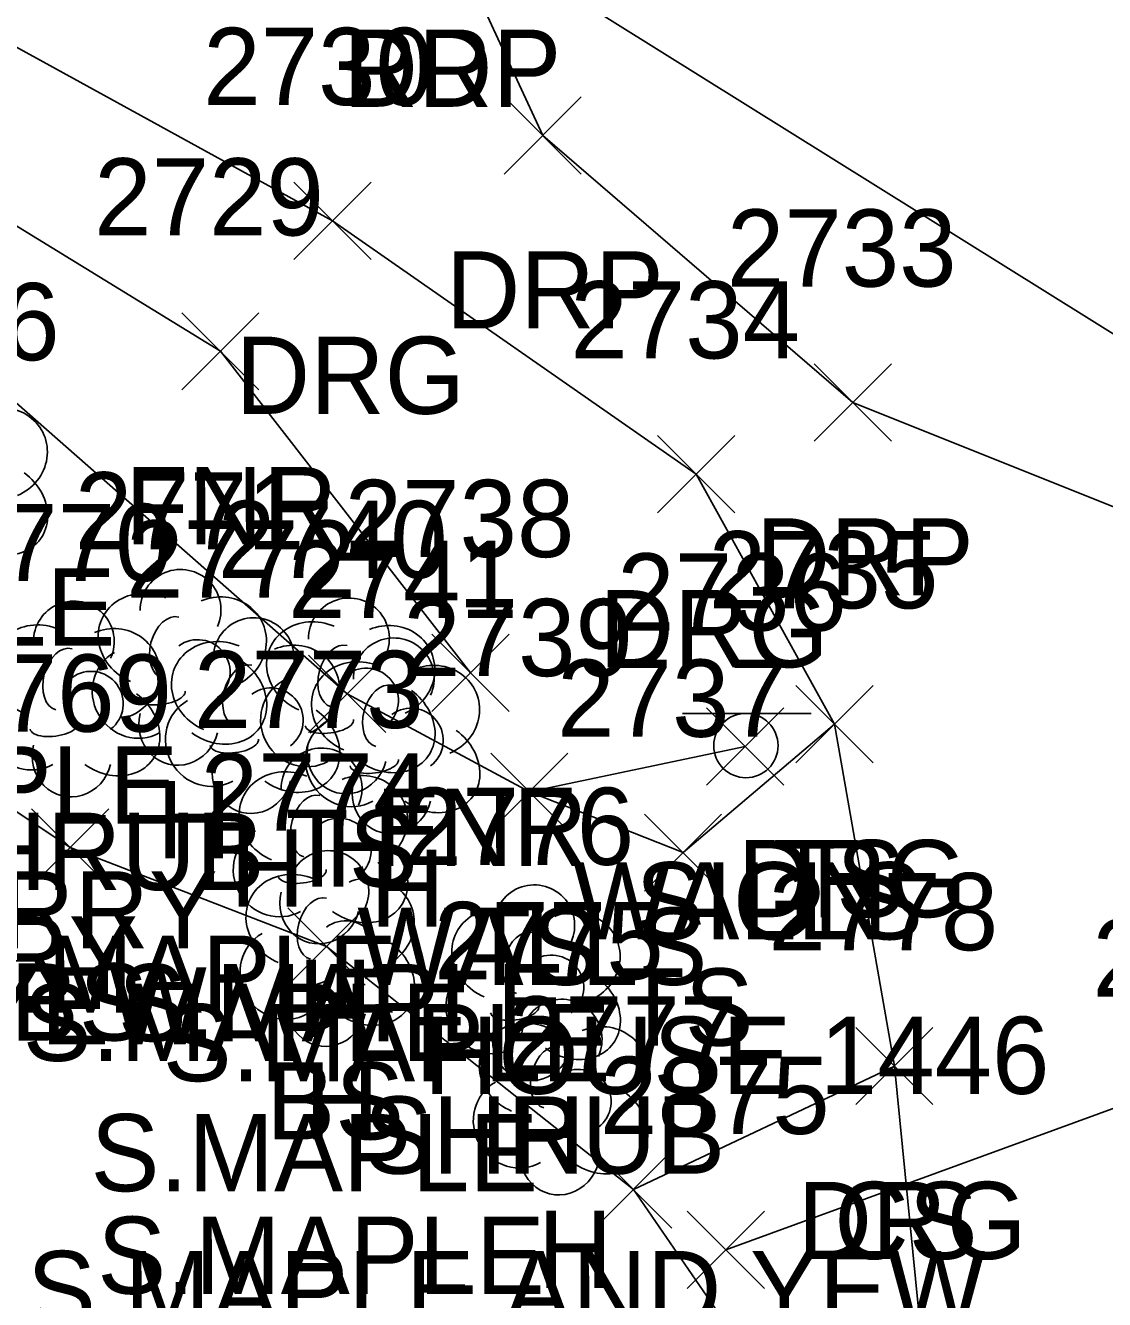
# Model space of a CAD drawing. Extents: x 1499292 to 1501024, y 534584 to 538043.
# Drawn here: x 1499640.28 to 1499668.23, y 537765.66 to 537798.66 of the extents above; entities that cross this region are included whole.
import ezdxf

# ---------------------------------------------------------------- set-up
doc = ezdxf.new("R2010")
doc.units = 0
for name, color, linetype in [('D_I', 7, 'Continuous'), ('D_TIC', 7, 'Continuous'), ('DCP', 7, 'Continuous'), ('L_A', 7, 'Continuous'), ('L_C', 7, 'Continuous'), ('L_I', 7, 'Continuous'), ('L_TIC', 7, 'Continuous'), ('LELB', 7, 'Continuous'), ('LFNC', 7, 'Continuous'), ('LSH', 7, 'Continuous'), ('LTD', 7, 'Continuous'), ('LWS', 7, 'Continuous'), ('P_A', 7, 'Continuous'), ('PET', 7, 'Continuous'), ('R_A', 7, 'Continuous'), ('R_I', 7, 'Continuous'), ('R_TIC', 7, 'Continuous'), ('RDG', 7, 'Continuous'), ('RDP', 7, 'Continuous'), ('S_A', 7, 'Continuous'), ('S_I', 7, 'Continuous'), ('SSGN', 7, 'Continuous'), ('U_C', 7, 'Continuous')]:
    doc.layers.add(name, color=color, linetype=linetype)

msp = doc.modelspace()

# ---------------------------------------------------------------- linework, layer by layer
at = {"layer": 'D_TIC'}
for points in [[(1499657.416, 537765.949), (1499659.416, 537767.949)], [(1499659.416, 537765.949), (1499657.416, 537767.949)]]:
    msp.add_lwpolyline(points, dxfattribs=at)
at = {"layer": 'DCP'}
msp.add_lwpolyline([(1499658.416, 537766.949), (1499674.076, 537772.661)], dxfattribs=at)
at = {"layer": 'L_TIC'}
for points in [[(1499644.323, 537789.222), (1499646.323, 537791.222)], [(1499646.323, 537789.222), (1499644.323, 537791.222)], [(1499650.803, 537780.891), (1499652.803, 537782.891)], [(1499652.803, 537780.891), (1499650.803, 537782.891)], [(1499647.607, 537780.35), (1499649.607, 537782.35)], [(1499649.607, 537780.35), (1499647.607, 537782.35)], [(1499647.607, 537780.35), (1499649.607, 537782.35)], [(1499649.607, 537780.35), (1499647.607, 537782.35)], [(1499660.233, 537779.563), (1499662.233, 537781.563)], [(1499662.233, 537779.563), (1499660.233, 537781.563)], [(1499657.918, 537778.987), (1499659.918, 537780.987)], [(1499659.918, 537778.987), (1499657.918, 537780.987)], [(1499652.328, 537777.808), (1499654.328, 537779.808)], [(1499654.328, 537777.808), (1499652.328, 537779.808)], [(1499652.328, 537777.808), (1499654.328, 537779.808)], [(1499654.328, 537777.808), (1499652.328, 537779.808)], [(1499640.436, 537776.369), (1499642.436, 537778.369)], [(1499642.436, 537776.369), (1499640.436, 537778.369)], [(1499656.308, 537776.236), (1499658.308, 537778.236)], [(1499658.308, 537776.236), (1499656.308, 537778.236)], [(1499647.073, 537773.807), (1499649.073, 537775.807)], [(1499649.073, 537773.807), (1499647.073, 537775.807)], [(1499661.782, 537770.708), (1499663.782, 537772.708)], [(1499663.782, 537770.708), (1499661.782, 537772.708)], [(1499655.022, 537767.512), (1499657.022, 537769.512)], [(1499657.022, 537767.512), (1499655.022, 537769.512)], [(1499655.022, 537767.512), (1499657.022, 537769.512)], [(1499657.022, 537767.512), (1499655.022, 537769.512)]]:
    msp.add_lwpolyline(points, dxfattribs=at)
at = {"layer": 'LELB'}
for points in [[(1499309.186, 537981.429), (1499342.601, 537967.946), (1499383.002, 537948.454), (1499403.335, 537937.322), (1499425.862, 537923.972), (1499462.056, 537903.885), (1499477.958, 537896.437), (1499498.482, 537885.281), (1499524.089, 537871.298), (1499544.155, 537861.141), (1499587.091, 537836.791), (1499598.177, 537827.35), (1499596, 537821.552), (1499610.739, 537811.692), (1499624.068, 537800.087), (1499630.641, 537795.692), (1499636.949, 537791.6), (1499648.607, 537781.35)], [(1499473.284, 537889.721), (1499498.471, 537879.808), (1499498.645, 537874.964), (1499522.472, 537856.451), (1499547.406, 537847.481), (1499543.068, 537839.362), (1499550.539, 537830.456), (1499554.894, 537825.457), (1499558.691, 537827.698), (1499558.309, 537830.261), (1499565.321, 537832.423), (1499575.95, 537829.995), (1499584.046, 537827.015), (1499587.206, 537819.565), (1499598.435, 537808.198), (1499610.893, 537797.818), (1499632.622, 537783.246), (1499641.436, 537777.369), (1499648.073, 537774.807), (1499656.022, 537768.512), (1499664.288, 537756.487)], [(1499661.233, 537780.563), (1499657.308, 537777.236), (1499653.328, 537778.808), (1499648.607, 537781.35)], [(1499656.022, 537768.512), (1499662.782, 537771.708)]]:
    msp.add_lwpolyline(points, dxfattribs=at)
at = {"layer": 'LFNC'}
msp.add_lwpolyline([(1499610.739, 537811.692), (1499626.25, 537801.938), (1499645.323, 537790.222), (1499651.803, 537781.891)], dxfattribs=at)
at = {"layer": 'LSH'}
for p, q in [((1499641.481, 537781.269), (1499641.481, 537781.269)), ((1499641.481, 537781.269), (1499641.481, 537781.269)), ((1499653.408, 537773.919), (1499653.408, 537773.919)), ((1499653.408, 537773.919), (1499653.408, 537773.919))]:
    msp.add_line(p, q, dxfattribs=at)
for centre in [(1499641.528, 537782.703), (1499653.454, 537775.353)]:
    msp.add_arc(centre, 1.047, 335.5272, 180.9563, dxfattribs=at)
for centre, major_axis, ratio, start_param, end_param in [((1499640.689, 537781.936), (1.21, -0.512), 0.895232, 1.570796, 4.712389), ((1499642.523, 537781.853), (-1.141, -0.483), 0.949671, 1.570796, 4.712389), ((1499641.273, 537781.727), (-0.208, -0.792), 0.645439, 3.141593, 6.283185), ((1499641.981, 537781.102), (-0.5, 0.667), 0.989748, 3.141593, 6.283185), ((1499640.398, 537780.56), (0.584, -1.042), 0.959034, 3.141593, 6.283185), ((1499642.481, 537780.436), (-1.09, 0.792), 0.841452, 1.570796, 4.712389), ((1499641.023, 537780.519), (-0.625, -0.083), 0.423636, 0, 3.141593), ((1499641.481, 537779.769), (0.265, 1.061), 0.942809, 1.570796, 4.712389), ((1499652.616, 537774.585), (1.21, -0.512), 0.895232, 1.570796, 4.712389), ((1499654.449, 537774.502), (-1.141, -0.483), 0.949671, 1.570796, 4.712389), ((1499653.199, 537774.377), (-0.208, -0.792), 0.645439, 3.141593, 6.283185), ((1499653.908, 537773.752), (-0.5, 0.667), 0.989748, 3.141593, 6.283185), ((1499652.324, 537773.21), (0.584, -1.042), 0.959034, 3.141593, 6.283185), ((1499654.408, 537773.086), (-1.09, 0.792), 0.841452, 1.570796, 4.712389), ((1499652.949, 537773.169), (-0.625, -0.083), 0.423636, 0, 3.141593), ((1499653.408, 537772.419), (0.265, 1.061), 0.942809, 1.570796, 4.712389)]:
    msp.add_ellipse(centre, major_axis=major_axis, ratio=ratio, start_param=start_param, end_param=end_param, dxfattribs=at)
at = {"layer": 'LTD'}
for p, q in [((1499644.247, 537782.089), (1499644.247, 537782.089)), ((1499644.247, 537782.089), (1499644.247, 537782.089)), ((1499648.607, 537781.35), (1499648.607, 537781.35)), ((1499648.607, 537781.35), (1499648.607, 537781.35)), ((1499646.142, 537780.84), (1499646.142, 537780.84)), ((1499646.142, 537780.84), (1499646.142, 537780.84)), ((1499649.769, 537780.315), (1499649.769, 537780.315)), ((1499649.769, 537780.315), (1499649.769, 537780.315)), ((1499647.899, 537777.464), (1499647.899, 537777.464)), ((1499647.899, 537777.464), (1499647.899, 537777.464)), ((1499648.073, 537774.807), (1499648.073, 537774.807)), ((1499648.073, 537774.807), (1499648.073, 537774.807)), ((1499653.408, 537773.919), (1499653.408, 537773.919)), ((1499653.408, 537773.919), (1499653.408, 537773.919)), ((1499654.117, 537770.958), (1499654.117, 537770.958)), ((1499654.117, 537770.958), (1499654.117, 537770.958))]:
    msp.add_line(p, q, dxfattribs=at)
for centre in [(1499644.293, 537783.523), (1499648.654, 537782.784), (1499646.189, 537782.274), (1499649.815, 537781.749), (1499647.946, 537778.898), (1499648.12, 537776.241), (1499653.454, 537775.353), (1499654.163, 537772.392)]:
    msp.add_arc(centre, 1.047, 335.5272, 180.9563, dxfattribs=at)
for centre, major_axis, ratio, start_param, end_param in [((1499639.614, 537787.573), (-1.141, -0.483), 0.949671, 1.570796, 4.712389), ((1499639.573, 537786.156), (-1.09, 0.792), 0.841452, 1.570796, 4.712389), ((1499643.455, 537782.756), (1.21, -0.512), 0.895232, 1.570796, 4.712389), ((1499645.288, 537782.673), (-1.141, -0.483), 0.949671, 1.570796, 4.712389), ((1499644.038, 537782.547), (-0.208, -0.792), 0.645439, 3.141593, 6.283185), ((1499647.816, 537782.016), (1.21, -0.512), 0.895232, 1.570796, 4.712389), ((1499649.649, 537781.933), (-1.141, -0.483), 0.949671, 1.570796, 4.712389), ((1499645.35, 537781.506), (1.21, -0.512), 0.895232, 1.570796, 4.712389), ((1499644.747, 537781.922), (-0.5, 0.667), 0.989748, 3.141593, 6.283185), ((1499647.183, 537781.423), (-1.141, -0.483), 0.949671, 1.570796, 4.712389), ((1499643.163, 537781.381), (0.584, -1.042), 0.959034, 3.141593, 6.283185), ((1499648.399, 537781.808), (-0.208, -0.792), 0.645439, 3.141593, 6.283185), ((1499645.247, 537781.256), (-1.09, 0.792), 0.841452, 1.570796, 4.712389), ((1499645.933, 537781.298), (-0.208, -0.792), 0.645439, 3.141593, 6.283185), ((1499648.977, 537780.982), (1.21, -0.512), 0.895232, 1.570796, 4.712389), ((1499649.107, 537781.183), (-0.5, 0.667), 0.989748, 3.141593, 6.283185), ((1499650.81, 537780.899), (-1.141, -0.483), 0.949671, 1.570796, 4.712389), ((1499643.788, 537781.339), (-0.625, -0.083), 0.423636, 0, 3.141593), ((1499646.642, 537780.673), (-0.5, 0.667), 0.989748, 3.141593, 6.283185), ((1499647.524, 537780.641), (0.584, -1.042), 0.959034, 3.141593, 6.283185), ((1499649.56, 537780.774), (-0.208, -0.792), 0.645439, 3.141593, 6.283185), ((1499649.607, 537780.517), (-1.09, 0.792), 0.841452, 1.570796, 4.712389), ((1499645.059, 537780.131), (0.584, -1.042), 0.959034, 3.141593, 6.283185), ((1499650.269, 537780.149), (-0.5, 0.667), 0.989748, 3.141593, 6.283185), ((1499644.247, 537780.589), (0.265, 1.061), 0.942809, 1.570796, 4.712389), ((1499647.142, 537780.007), (-1.09, 0.792), 0.841452, 1.570796, 4.712389), ((1499648.685, 537779.607), (0.584, -1.042), 0.959034, 3.141593, 6.283185), ((1499648.149, 537780.6), (-0.625, -0.083), 0.423636, 0, 3.141593), ((1499645.684, 537780.09), (-0.625, -0.083), 0.423636, 0, 3.141593), ((1499648.608, 537779.85), (0.265, 1.061), 0.942809, 1.570796, 4.712389), ((1499650.769, 537779.482), (-1.09, 0.792), 0.841452, 1.570796, 4.712389), ((1499646.142, 537779.34), (0.265, 1.061), 0.942809, 1.570796, 4.712389), ((1499647.107, 537778.131), (1.21, -0.512), 0.895232, 1.570796, 4.712389), ((1499649.31, 537779.565), (-0.625, -0.083), 0.423636, 0, 3.141593), ((1499648.941, 537778.048), (-1.141, -0.483), 0.949671, 1.570796, 4.712389), ((1499647.691, 537777.923), (-0.208, -0.792), 0.645439, 3.141593, 6.283185), ((1499649.769, 537778.815), (0.265, 1.061), 0.942809, 1.570796, 4.712389), ((1499648.399, 537777.298), (-0.5, 0.667), 0.989748, 3.141593, 6.283185), ((1499646.816, 537776.756), (0.584, -1.042), 0.959034, 3.141593, 6.283185), ((1499648.899, 537776.631), (-1.09, 0.792), 0.841452, 1.570796, 4.712389), ((1499647.281, 537775.473), (1.21, -0.512), 0.895232, 1.570796, 4.712389), ((1499647.441, 537776.714), (-0.625, -0.083), 0.423636, 0, 3.141593), ((1499649.115, 537775.39), (-1.141, -0.483), 0.949671, 1.570796, 4.712389), ((1499647.899, 537775.964), (0.265, 1.061), 0.942809, 1.570796, 4.712389), ((1499647.865, 537775.265), (-0.208, -0.792), 0.645439, 3.141593, 6.283185), ((1499652.616, 537774.585), (1.21, -0.512), 0.895232, 1.570796, 4.712389), ((1499654.449, 537774.502), (-1.141, -0.483), 0.949671, 1.570796, 4.712389), ((1499648.573, 537774.64), (-0.5, 0.667), 0.989748, 3.141593, 6.283185), ((1499646.99, 537774.098), (0.584, -1.042), 0.959034, 3.141593, 6.283185), ((1499653.199, 537774.377), (-0.208, -0.792), 0.645439, 3.141593, 6.283185), ((1499649.073, 537773.973), (-1.09, 0.792), 0.841452, 1.570796, 4.712389), ((1499653.908, 537773.752), (-0.5, 0.667), 0.989748, 3.141593, 6.283185), ((1499652.324, 537773.21), (0.584, -1.042), 0.959034, 3.141593, 6.283185), ((1499647.615, 537774.057), (-0.625, -0.083), 0.423636, 0, 3.141593), ((1499654.408, 537773.086), (-1.09, 0.792), 0.841452, 1.570796, 4.712389), ((1499648.074, 537773.307), (0.265, 1.061), 0.942809, 1.570796, 4.712389), ((1499652.949, 537773.169), (-0.625, -0.083), 0.423636, 0, 3.141593), ((1499653.325, 537771.625), (1.21, -0.512), 0.895232, 1.570796, 4.712389), ((1499655.158, 537771.542), (-1.141, -0.483), 0.949671, 1.570796, 4.712389), ((1499653.408, 537772.419), (0.265, 1.061), 0.942809, 1.570796, 4.712389), ((1499653.908, 537771.417), (-0.208, -0.792), 0.645439, 3.141593, 6.283185), ((1499654.617, 537770.792), (-0.5, 0.667), 0.989748, 3.141593, 6.283185), ((1499653.033, 537770.25), (0.584, -1.042), 0.959034, 3.141593, 6.283185), ((1499655.117, 537770.125), (-1.09, 0.792), 0.841452, 1.570796, 4.712389), ((1499653.658, 537770.208), (-0.625, -0.083), 0.423636, 0, 3.141593), ((1499654.117, 537769.458), (0.265, 1.061), 0.942809, 1.570796, 4.712389)]:
    msp.add_ellipse(centre, major_axis=major_axis, ratio=ratio, start_param=start_param, end_param=end_param, dxfattribs=at)
at = {"layer": 'LWS'}
msp.add_lwpolyline([(1499658.918, 537779.987), (1499653.328, 537778.808)], dxfattribs=at)
at = {"layer": 'PET'}
msp.add_lwpolyline([(1499310.023, 537983.746), (1499343.075, 537969.541), (1499383.731, 537949.439), (1499427.71, 537927.425), (1499464.171, 537907.983), (1499500.199, 537887.497), (1499544.495, 537863.142), (1499587.74, 537838.677), (1499616.247, 537822.183), (1499651.021, 537801.554), (1499676.536, 537785.628), (1499704.158, 537768.574), (1499722.55, 537756.398), (1499745.414, 537739.8), (1499767.298, 537722.36), (1499790.892, 537701.646), (1499806.057, 537686.036), (1499813.912, 537693.068), (1499820.533, 537699.08)], dxfattribs=at)
at = {"layer": 'R_TIC'}
for points in [[(1499652.673, 537794.813), (1499654.673, 537796.813)], [(1499654.673, 537794.813), (1499652.673, 537796.813)], [(1499647.228, 537792.601), (1499649.228, 537794.601)], [(1499649.228, 537792.601), (1499647.228, 537794.601)], [(1499660.704, 537787.897), (1499662.704, 537789.897)], [(1499662.704, 537787.897), (1499660.704, 537789.897)], [(1499656.65, 537786.037), (1499658.65, 537788.037)], [(1499658.65, 537786.037), (1499656.65, 537788.037)], [(1499660.233, 537779.563), (1499662.233, 537781.563)], [(1499662.233, 537779.563), (1499660.233, 537781.563)], [(1499661.782, 537770.708), (1499663.782, 537772.708)], [(1499663.782, 537770.708), (1499661.782, 537772.708)]]:
    msp.add_lwpolyline(points, dxfattribs=at)
at = {"layer": 'RDG'}
msp.add_lwpolyline([(1499616.247, 537822.183), (1499611.438, 537814.178), (1499627.998, 537804.719), (1499648.228, 537793.601), (1499657.65, 537787.037), (1499661.233, 537780.563), (1499662.782, 537771.708), (1499664.288, 537756.487), (1499660.39, 537740.632), (1499648.725, 537728.571), (1499635.519, 537714.664), (1499643.061, 537703.46), (1499654.084, 537709.775), (1499666.097, 537716.349), (1499687.017, 537701.096), (1499694.358, 537709.594), (1499686.467, 537716.113), (1499685.219, 537725.482), (1499686.936, 537727.795), (1499688.073, 537727.086)], dxfattribs=at)
at = {"layer": 'RDP'}
msp.add_lwpolyline([(1499651.021, 537801.554), (1499653.673, 537795.813), (1499661.704, 537788.897), (1499671.052, 537785.153), (1499673.505, 537786.342), (1499676.536, 537785.628)], dxfattribs=at)
at = {"layer": 'SSGN'}
for p, q in [((1499657.29, 537780.841), (1499660.624, 537780.841)), ((1499658.937, 537780.008), (1499658.937, 537780.008))]:
    msp.add_line(p, q, dxfattribs=at)
msp.add_circle((1499658.937, 537780.008), 0.833, dxfattribs=at)

# ---------------------------------------------------------------- texts
at = {"layer": 'D_I'}
msp.add_text('2875', height=2, dxfattribs=at).set_placement((1499655.156, 537769.949))
at = {"layer": 'L_A'}
for s, p in [('FNR', (1499642.859, 537785.222)), ('H', (1499643.68, 537777.089)), ('FNR', (1499649.339, 537776.891)), ('SHRUB', (1499637.111, 537776.269)), ('TS', (1499647.017, 537776.35)), ('TS', (1499647.017, 537776.35)), ('H', (1499648.04, 537776.35)), ('H', (1499645.575, 537775.84)), ('TS', (1499659.642, 537775.563)), ('H', (1499649.202, 537775.315)), ('WALLS', (1499654.461, 537774.987)), ('WALLS', (1499648.871, 537773.808)), ('TS', (1499651.737, 537773.808)), ('BS', (1499639.877, 537772.369)), ('H', (1499647.332, 537772.464)), ('TS', (1499655.718, 537772.236)), ('BS', (1499646.514, 537769.807)), ('H', (1499647.506, 537769.807)), ('SHRUB', (1499649.038, 537768.919)), ('H', (1499652.841, 537768.919)), ('CS', (1499661.223, 537766.708)), ('H', (1499653.55, 537765.958))]:
    msp.add_text(s, height=2, dxfattribs=at).set_placement(p)
at = {"layer": 'L_C'}
for s, p in [('S.MAPLE', (1499631.012, 537782.6)), ('S.MAPLE', (1499632.636, 537777.99)), ('3 S.CHERRY', (1499629.207, 537774.753)), ('4 S.CHERRY', (1499627.131, 537773.582)), ('S.MAPLE', (1499638.31, 537773.089)), ('YEW', (1499638.883, 537772.269)), ('S.MAPLE', (1499642.67, 537772.35)), ('S.MAPLE', (1499640.205, 537771.84)), ('S.MAPLE', (1499643.832, 537771.315)), ('HOUSE 1446', (1499650.595, 537770.987)), ('S.MAPLE', (1499641.962, 537768.464)), ('S.MAPLE', (1499642.136, 537765.807)), ('2 S.MAPLE AND YEW', (1499638.085, 537764.919))]:
    msp.add_text(s, height=2, dxfattribs=at).set_placement(p)
at = {"layer": 'L_I'}
for s, p in [('2729', (1499642.056, 537793.222)), ('2766', (1499635.211, 537789.99)), ('2771', (1499641.554, 537785.089)), ('2738', (1499648.544, 537784.891)), ('2740', (1499645.261, 537784.35)), ('2740', (1499645.261, 537784.35)), ('2740', (1499645.261, 537784.35)), ('2770', (1499638.135, 537784.269)), ('2772', (1499642.882, 537783.84)), ('2735', (1499657.973, 537783.563)), ('2741', (1499647.076, 537783.315)), ('2736', (1499655.603, 537782.987)), ('2739', (1499650.06, 537781.808)), ('2739', (1499650.06, 537781.808)), ('2769', (1499638.121, 537780.369)), ('2773', (1499644.639, 537780.464)), ('2737', (1499654.048, 537780.236)), ('2774', (1499644.813, 537777.807)), ('2774', (1499644.813, 537777.807)), ('2776', (1499650.093, 537776.919)), ('2776', (1499650.093, 537776.919)), ('2778', (1499659.522, 537774.708)), ('2775', (1499650.857, 537773.958)), ('2777', (1499652.763, 537771.512)), ('2777', (1499652.763, 537771.512))]:
    msp.add_text(s, height=2, dxfattribs=at).set_placement(p)
at = {"layer": 'P_A'}
msp.add_text('RDP', height=2, dxfattribs=at).set_placement((1499648.509, 537796.554))
at = {"layer": 'R_A'}
for s, p in [('DRP', (1499648.509, 537796.554)), ('DRP', (1499651.161, 537790.813)), ('DRG', (1499645.716, 537788.601)), ('DRP', (1499659.192, 537783.897)), ('DRG', (1499655.138, 537782.037)), ('DRG', (1499658.721, 537775.563)), ('DRG', (1499660.27, 537766.708))]:
    msp.add_text(s, height=2, dxfattribs=at).set_placement(p)
at = {"layer": 'R_I'}
for s, p in [('2730', (1499644.881, 537796.601)), ('2733', (1499658.444, 537791.897)), ('2734', (1499654.39, 537790.037)), ('2735', (1499657.973, 537783.563)), ('2778', (1499659.522, 537774.708))]:
    msp.add_text(s, height=2, dxfattribs=at).set_placement(p)
at = {"layer": 'S_A'}
msp.add_text('SIGN', height=2, dxfattribs=at).set_placement((1499656.075, 537774.987))
at = {"layer": 'S_I'}
msp.add_text('2736', height=2, dxfattribs=at).set_placement((1499655.603, 537782.987))
at = {"layer": 'U_C'}
msp.add_text('2/12-6-1/3', height=2, dxfattribs=at).set_placement((1499667.913, 537773.508))

doc.saveas('drawing.dxf')
